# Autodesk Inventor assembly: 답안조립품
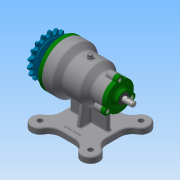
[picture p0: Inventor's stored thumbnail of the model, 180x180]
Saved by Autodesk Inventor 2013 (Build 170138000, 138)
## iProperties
Created: 2017-03
Part Number: 답안조립품
Document SubType Name: Assembly
Designer: Administrator
Author: Administrator
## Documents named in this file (14)
- C:\Users\Administrator\Desktop\470307V1016\답안조립품.iam
- C:\Users\Administrator\Desktop\470307V1016\본체-1.ipt
- C:\Users\Administrator\Desktop\470307V1016\볼트 M4 x 12.ipt
- C:\Users\Administrator\Desktop\470307V1016\볼트 M5 x 10.ipt
- 볼트 M5 x 10.ipt
- C:\Users\Administrator\Desktop\470307V1016\스프로킷.ipt
- C:\Users\Administrator\Desktop\470307V1016\앞커버.ipt
- C:\Users\Administrator\Desktop\470307V1016\오일 실 10 20 7.ipt
- C:\Users\Administrator\Desktop\470307V1016\오일 실 17 30 8.ipt
- C:\Users\Administrator\Desktop\470307V1016\축.ipt
- C:\Users\Administrator\Desktop\470307V1016\키5x5.ipt
- C:\Users\Administrator\Desktop\470307V1016\뒤커버.ipt
- C:\Users\Administrator\Desktop\470307V1016\베어링-6203.ipt
- C:\Users\Administrator\Desktop\470307V1016\베어링-6200.ipt
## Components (9 placed, 1 different names)
1. ISO 4762 M4 x 12:1
2. ISO 4762 M4 x 12:5
3. ISO 4762 M4 x 12:6
4. ISO 4762 M4 x 12:7
5. ISO 4762 M4 x 12:8
6. ISO 4762 M4 x 12:9
7. ISO 4762 M4 x 12:2
8. ISO 4762 M4 x 12:10
9. ISO 4762 M4 x 12:11
